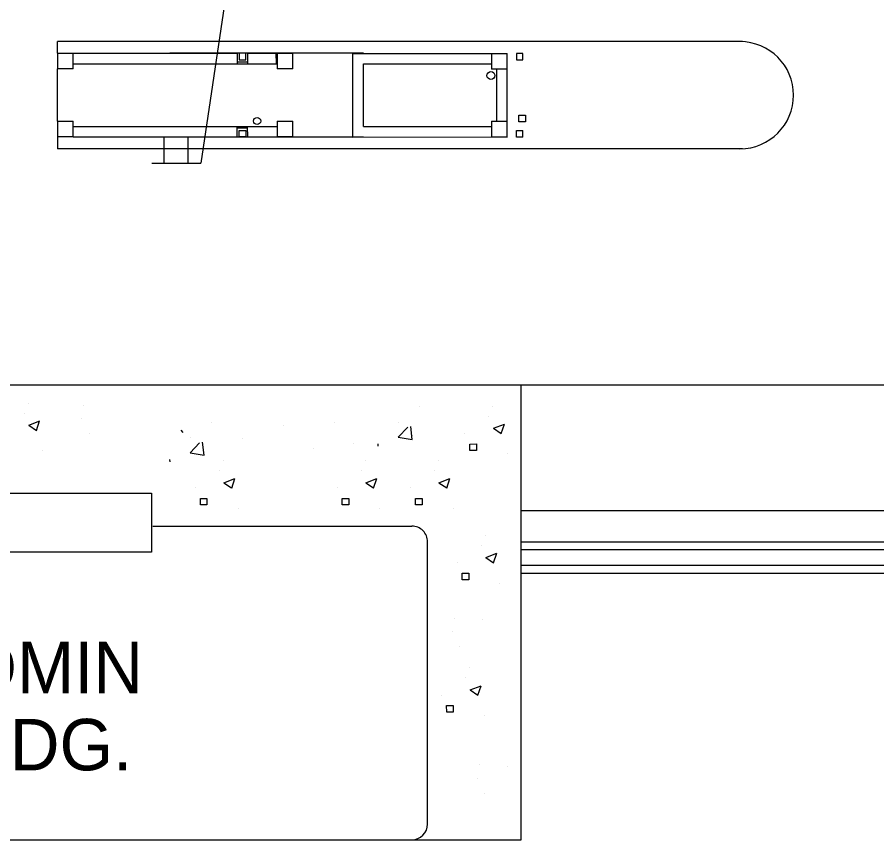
# Model space of a CAD drawing. Extents: x 524708 to 525490, y 1531861 to 1532506.
# Drawn here: x 525161.4 to 525219.9, y 1532238.3 to 1532294.3 of the extents above; entities that cross this region are included whole.
import ezdxf

# ---------------------------------------------------------------- set-up
doc = ezdxf.new("R2010")
doc.units = 0
for name, color, linetype in [('Guardrail', 7, 'Continuous'), ('LeaderLine_dp', 7, 'Continuous'), ('RoadwayMisc', 7, 'Continuous'), ('SignSupport', 7, 'Continuous'), ('TextLabel', 7, 'Continuous')]:
    doc.layers.add(name, color=color, linetype=linetype)

msp = doc.modelspace()

# ---------------------------------------------------------------- linework, layer by layer
at = {"layer": 'Guardrail'}
msp.add_line((525195.727, 1532256.467), (525319.12, 1532256.467), dxfattribs=at)
at = {"layer": 'LeaderLine_dp'}
msp.add_line((525186.332, 1532367.988), (525173.939, 1532284.368), dxfattribs=at)
at = {"layer": 'RoadwayMisc'}
for p, q in [((525210.791, 1532292.647), (525164.181, 1532292.646)), ((525164.182, 1532291.851), (525164.181, 1532292.646)), ((525164.182, 1532291.851), (525164.181, 1532290.785)), ((525164.182, 1532291.851), (525165.25, 1532291.851)), ((525165.248, 1532290.784), (525165.25, 1532291.851)), ((525165.25, 1532291.852), (525176.41, 1532291.851)), ((525184.994, 1532291.852), (525171.831, 1532291.853)), ((525176.41, 1532291.851), (525176.412, 1532291.141)), ((525176.989, 1532291.852), (525176.545, 1532291.852)), ((525176.545, 1532291.852), (525176.545, 1532291.407)), ((525176.545, 1532291.407), (525176.989, 1532291.407)), ((525176.989, 1532291.407), (525176.989, 1532291.852)), ((525177.122, 1532291.852), (525179.124, 1532291.852)), ((525177.122, 1532291.852), (525177.123, 1532291.141)), ((525179.05, 1532291.852), (525179.052, 1532291.147)), ((525179.124, 1532291.852), (525180.192, 1532291.852)), ((525179.124, 1532291.852), (525179.124, 1532290.786)), ((525180.192, 1532290.785), (525180.192, 1532291.852)), ((525184.283, 1532291.846), (525193.713, 1532291.845)), ((525184.284, 1532286.153), (525184.283, 1532291.846)), ((525193.713, 1532291.845), (525194.779, 1532291.845)), ((525193.713, 1532291.845), (525194.779, 1532291.845)), ((525193.713, 1532291.845), (525193.713, 1532290.778)), ((525194.779, 1532290.779), (525194.779, 1532291.845)), ((525195.848, 1532291.847), (525195.401, 1532291.846)), ((525195.401, 1532291.846), (525195.403, 1532291.403)), ((525195.403, 1532291.403), (525195.848, 1532291.401)), ((525195.848, 1532291.401), (525195.847, 1532291.845)), ((525195.848, 1532291.401), (525195.848, 1532291.847)), ((525165.249, 1532291.141), (525179.124, 1532291.141)), ((525170.955, 1532291.141), (525179.124, 1532291.141)), ((525177.124, 1532291.251), (525176.413, 1532291.252)), ((525184.995, 1532286.865), (525184.994, 1532291.135)), ((525184.994, 1532291.135), (525193.711, 1532291.135)), ((525164.18, 1532287.227), (525164.181, 1532290.785)), ((525165.248, 1532290.784), (525164.181, 1532290.785)), ((525180.192, 1532290.785), (525179.124, 1532290.786)), ((525194.779, 1532290.779), (525193.713, 1532290.778)), ((525194.068, 1532287.22), (525194.068, 1532290.779)), ((525194.78, 1532287.221), (525194.779, 1532290.779)), ((525195.58, 1532287.191), (525195.581, 1532287.635)), ((525195.581, 1532287.635), (525196.025, 1532287.635)), ((525196.025, 1532287.635), (525196.025, 1532287.189)), ((525164.18, 1532287.227), (525165.247, 1532287.228)), ((525164.18, 1532287.227), (525164.181, 1532286.159)), ((525165.248, 1532286.16), (525165.247, 1532287.228)), ((525165.247, 1532286.868), (525172.009, 1532286.871)), ((525172.009, 1532286.871), (525174.411, 1532286.871)), ((525174.411, 1532286.871), (525179.124, 1532286.872)), ((525174.411, 1532286.871), (525179.124, 1532286.872)), ((525176.413, 1532286.159), (525176.412, 1532286.871)), ((525177.124, 1532286.759), (525176.412, 1532286.759)), ((525177.124, 1532286.16), (525177.123, 1532286.871)), ((525179.125, 1532287.228), (525180.193, 1532287.228)), ((525179.125, 1532287.228), (525179.125, 1532286.159)), ((525180.193, 1532286.16), (525180.193, 1532287.228)), ((525184.995, 1532286.865), (525193.712, 1532286.866)), ((525193.712, 1532287.221), (525194.78, 1532287.221)), ((525193.712, 1532287.221), (525193.712, 1532286.154)), ((525194.78, 1532286.152), (525194.78, 1532287.221)), ((525196.025, 1532287.189), (525195.58, 1532287.191)), ((525165.248, 1532286.16), (525164.181, 1532286.159)), ((525164.181, 1532286.159), (525164.182, 1532285.353)), ((525165.248, 1532286.157), (525172.01, 1532286.16)), ((525171.829, 1532286.159), (525184.996, 1532286.16)), ((525172.01, 1532286.16), (525174.41, 1532286.159)), ((525174.41, 1532286.159), (525176.413, 1532286.159)), ((525176.545, 1532286.159), (525176.547, 1532286.604)), ((525176.988, 1532286.16), (525176.545, 1532286.159)), ((525176.547, 1532286.604), (525176.989, 1532286.604)), ((525176.989, 1532286.604), (525176.988, 1532286.16)), ((525177.124, 1532286.16), (525179.125, 1532286.159)), ((525180.193, 1532286.16), (525179.125, 1532286.159)), ((525184.284, 1532286.153), (525193.712, 1532286.154)), ((525194.78, 1532286.152), (525193.712, 1532286.154)), ((525193.712, 1532286.154), (525194.78, 1532286.152)), ((525195.402, 1532286.152), (525195.403, 1532286.6)), ((525195.849, 1532286.153), (525195.402, 1532286.152)), ((525195.403, 1532286.6), (525195.847, 1532286.599)), ((525195.849, 1532286.153), (525195.847, 1532286.599)), ((525210.79, 1532285.352), (525164.182, 1532285.353)), ((525201.434, 1532285.353), (525197.922, 1532285.352)), ((525204.638, 1532285.352), (525204.638, 1532285.352)), ((525028.445, 1532269.281), (525319.12, 1532269.281)), ((525195.727, 1532238.313), (525195.727, 1532269.281)), ((525162.195, 1532268.038), (525162.195, 1532268.038)), ((525165.952, 1532267.894), (525165.952, 1532267.894)), ((525188.785, 1532267.786), (525188.785, 1532267.786)), ((525193.813, 1532267.82), (525193.813, 1532267.82)), ((525161.909, 1532267.362), (525161.909, 1532267.362)), ((525162.225, 1532266.541), (525162.973, 1532266.828)), ((525162.757, 1532266.182), (525162.972, 1532266.828)), ((525165.821, 1532266.994), (525165.821, 1532266.994)), ((525193.527, 1532267.144), (525193.527, 1532267.144)), ((525162.225, 1532266.541), (525162.755, 1532266.185)), ((525174.629, 1532266.72), (525174.629, 1532266.72)), ((525179.579, 1532266.526), (525179.579, 1532266.526)), ((525183.012, 1532266.731), (525183.012, 1532266.731)), ((525187.366, 1532265.72), (525188.012, 1532266.394)), ((525187.39, 1532266.751), (525187.39, 1532266.751)), ((525188.315, 1532265.573), (525188.215, 1532266.438)), ((525193.843, 1532266.323), (525194.591, 1532266.61)), ((525193.843, 1532266.323), (525194.373, 1532265.967)), ((525194.375, 1532265.965), (525194.59, 1532266.61)), ((525166.35, 1532265.961), (525166.35, 1532265.961)), ((525172.741, 1532266.041), (525172.593, 1532266.188)), ((525173.234, 1532265.685), (525173.234, 1532265.685)), ((525176.784, 1532265.663), (525176.784, 1532265.663)), ((525187.366, 1532265.72), (525188.313, 1532265.572)), ((525188.343, 1532265.828), (525188.343, 1532265.828)), ((525191.892, 1532265.975), (525191.892, 1532265.975)), ((525173.209, 1532264.654), (525173.856, 1532265.328)), ((525174.159, 1532264.507), (525174.059, 1532265.372)), ((525184.298, 1532265.295), (525184.298, 1532265.295)), ((525186.01, 1532265.105), (525185.99, 1532265.271)), ((525192.247, 1532265.256), (525192.693, 1532265.257)), ((525192.248, 1532264.813), (525192.247, 1532265.256)), ((525192.693, 1532265.257), (525192.693, 1532264.811)), ((525163.19, 1532264.798), (525163.19, 1532264.798)), ((525173.209, 1532264.654), (525174.157, 1532264.506)), ((525181.624, 1532264.942), (525181.624, 1532264.942)), ((525192.693, 1532264.811), (525192.248, 1532264.813)), ((525194.808, 1532264.58), (525194.808, 1532264.58)), ((525171.853, 1532264.039), (525171.833, 1532264.205)), ((525175.474, 1532264.115), (525175.474, 1532264.115)), ((525185.123, 1532264.115), (525185.123, 1532264.115)), ((525190.107, 1532264.115), (525190.107, 1532264.115)), ((525175.188, 1532263.439), (525175.188, 1532263.439)), ((525184.837, 1532263.439), (525184.837, 1532263.439)), ((525189.82, 1532263.439), (525189.82, 1532263.439)), ((525175.504, 1532262.618), (525176.252, 1532262.905)), ((525176.036, 1532262.259), (525176.251, 1532262.904)), ((525185.153, 1532262.618), (525185.901, 1532262.905)), ((525185.685, 1532262.259), (525185.9, 1532262.904)), ((525190.136, 1532262.618), (525190.884, 1532262.905)), ((525190.669, 1532262.259), (525190.883, 1532262.904)), ((525173.554, 1532262.27), (525173.554, 1532262.27)), ((525175.504, 1532262.618), (525176.034, 1532262.262)), ((525183.203, 1532262.27), (525183.203, 1532262.27)), ((525185.153, 1532262.618), (525185.683, 1532262.262)), ((525188.186, 1532262.27), (525188.186, 1532262.27)), ((525190.136, 1532262.618), (525190.666, 1532262.262)), ((525173.909, 1532261.551), (525174.354, 1532261.552)), ((525173.91, 1532261.108), (525173.909, 1532261.551)), ((525174.354, 1532261.106), (525173.91, 1532261.108)), ((525174.354, 1532261.552), (525174.354, 1532261.106)), ((525183.557, 1532261.551), (525184.003, 1532261.552)), ((525183.559, 1532261.108), (525183.557, 1532261.551)), ((525184.003, 1532261.106), (525183.559, 1532261.108)), ((525184.003, 1532261.552), (525184.003, 1532261.106)), ((525188.541, 1532261.551), (525188.986, 1532261.552)), ((525188.542, 1532261.108), (525188.541, 1532261.551)), ((525188.986, 1532261.106), (525188.542, 1532261.108)), ((525188.986, 1532261.552), (525188.986, 1532261.106)), ((525176.469, 1532260.875), (525176.469, 1532260.875)), ((525186.118, 1532260.875), (525186.118, 1532260.875)), ((525191.101, 1532260.875), (525191.101, 1532260.875)), ((525195.727, 1532260.738), (525319.12, 1532260.738)), ((525170.664, 1532259.67), (525188.294, 1532259.67)), ((525193.287, 1532259.025), (525193.287, 1532259.025)), ((525189.361, 1532239.381), (525189.361, 1532258.602)), ((525193.001, 1532258.35), (525193.001, 1532258.35)), ((525195.727, 1532258.602), (525319.12, 1532258.602)), ((525195.727, 1532258.068), (525319.12, 1532258.068)), ((525193.317, 1532257.528), (525194.065, 1532257.815)), ((525193.317, 1532257.528), (525193.847, 1532257.173)), ((525193.849, 1532257.17), (525194.064, 1532257.815)), ((525191.367, 1532257.18), (525191.367, 1532257.18)), ((525195.727, 1532257), (525319.12, 1532257)), ((525191.722, 1532256.462), (525192.167, 1532256.463)), ((525191.723, 1532256.019), (525191.722, 1532256.462)), ((525192.167, 1532256.463), (525192.167, 1532256.017)), ((525192.167, 1532256.017), (525191.723, 1532256.019)), ((525194.282, 1532255.786), (525194.282, 1532255.786)), ((525191.165, 1532253.377), (525191.165, 1532253.377)), ((525193.108, 1532253.28), (525193.108, 1532253.28)), ((525191.034, 1532252.476), (525191.034, 1532252.476)), ((525191.563, 1532251.444), (525191.563, 1532251.444)), ((525192.227, 1532250.013), (525192.227, 1532250.013)), ((525191.941, 1532249.337), (525191.941, 1532249.337)), ((525192.257, 1532248.516), (525193.005, 1532248.803)), ((525192.789, 1532248.157), (525193.004, 1532248.803)), ((525190.307, 1532248.168), (525190.307, 1532248.168)), ((525192.257, 1532248.516), (525192.787, 1532248.16)), ((525190.661, 1532247.449), (525191.107, 1532247.45)), ((525190.663, 1532247.006), (525190.661, 1532247.449)), ((525191.107, 1532247.004), (525190.663, 1532247.006)), ((525191.107, 1532247.45), (525191.107, 1532247.004)), ((525193.222, 1532246.773), (525193.222, 1532246.773)), ((525192.862, 1532243.41), (525192.862, 1532243.41)), ((525194.805, 1532243.313), (525194.805, 1532243.313)), ((525192.73, 1532242.51), (525192.73, 1532242.51)), ((525193.259, 1532241.477), (525193.259, 1532241.477)), ((525135.968, 1532238.313), (525188.294, 1532238.313)), ((525188.294, 1532238.313), (525195.727, 1532238.313))]:
    msp.add_line(p, q, dxfattribs=at)
msp.add_lwpolyline([(525159.91, 1532261.907), (525170.589, 1532261.907), (525170.589, 1532257.901), (525159.91, 1532257.901)], close=True, dxfattribs=at)
for centre, radius in [((525193.671, 1532290.337), 0.267), ((525177.763, 1532287.242), 0.245)]:
    msp.add_circle(centre, radius, dxfattribs=at)
for centre, radius, start, end in [((525210.612, 1532289), 3.647, 269.99999, 89.99999), ((525188.294, 1532258.602), 1.068, 359.99999, 90.00004), ((525188.294, 1532239.381), 1.068, 270.00004, 359.99999)]:
    msp.add_arc(centre, radius, start, end, dxfattribs=at)
at = {"layer": 'SignSupport'}
for p, q in [((525171.45, 1532284.368), (525171.45, 1532286.16)), ((525173.083, 1532284.368), (525173.083, 1532286.16)), ((525170.594, 1532284.368), (525173.939, 1532284.368))]:
    msp.add_line(p, q, dxfattribs=at)

# ---------------------------------------------------------------- texts
at = {"layer": 'TextLabel'}
for s, p in [('ADMIN', (525154.925, 1532248.293)), ('BLDG.', (525155.219, 1532243.043))]:
    msp.add_text(s, height=3.5, rotation=359.99999, dxfattribs=at).set_placement(p)

doc.saveas('drawing.dxf')
